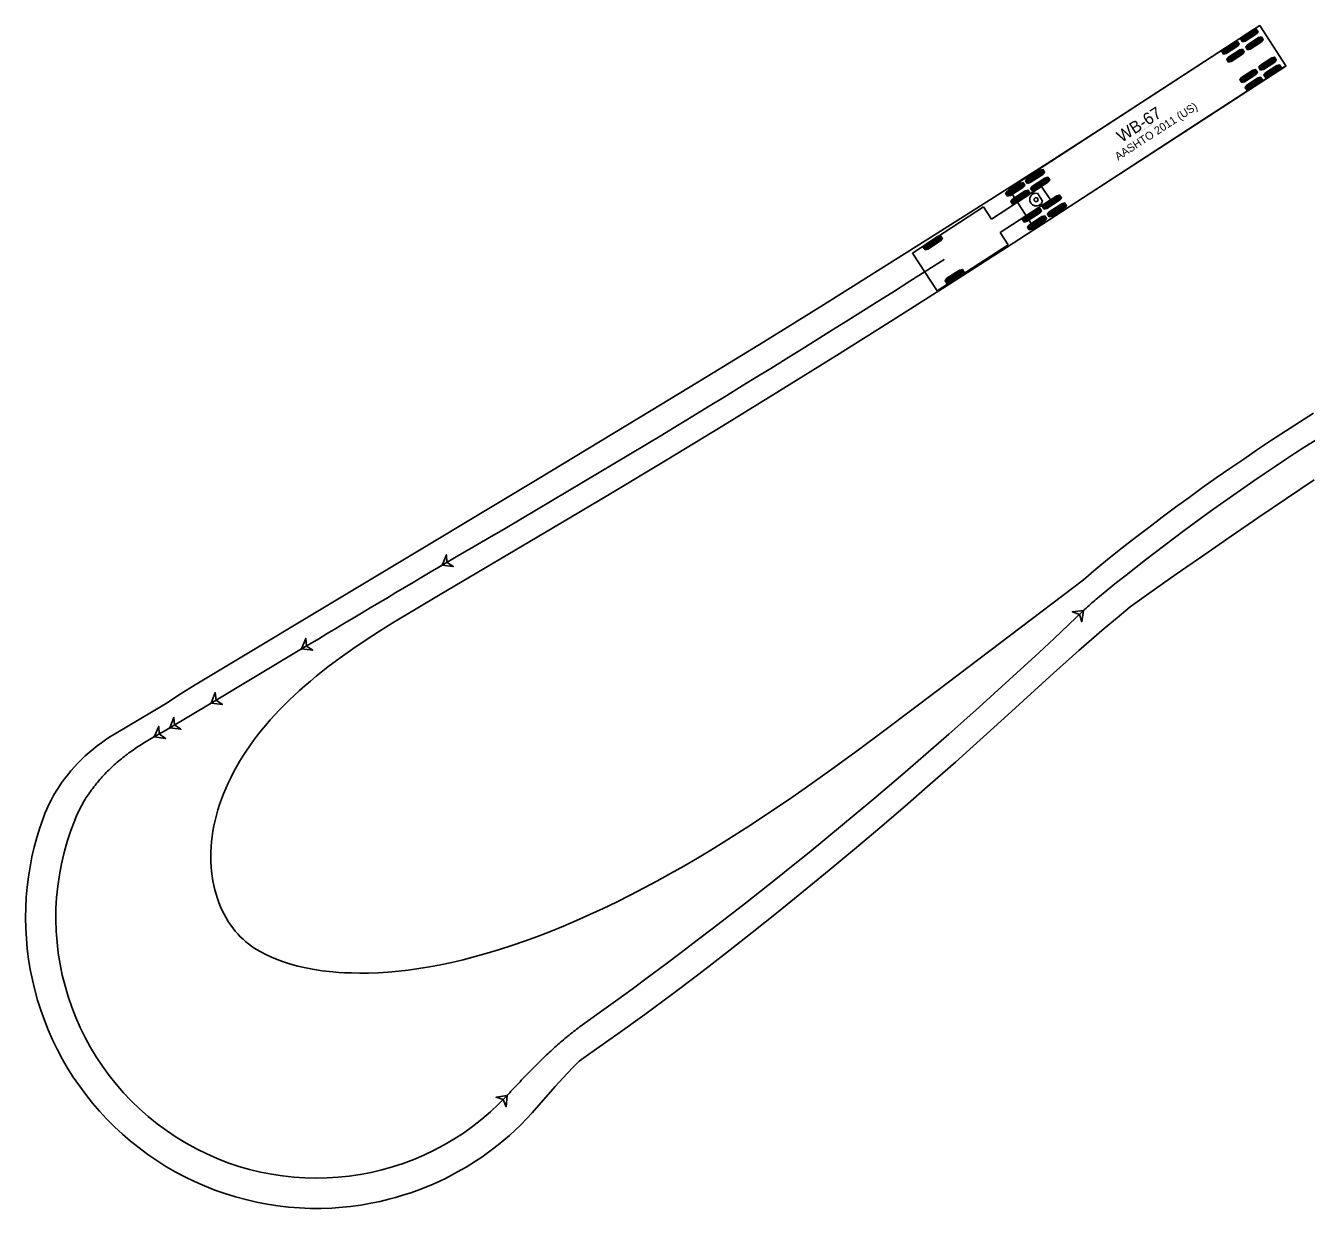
# Model space of a CAD drawing. Extents: x 2175591 to 2194071, y 76570 to 86955.
# Drawn here: x 2175590.5 to 2175817.3, y 76570.3 to 76779.7 of the extents above; entities that cross this region are included whole.
import ezdxf

# ---------------------------------------------------------------- set-up
doc = ezdxf.new("R2010")
doc.units = 0
doc.layers.add('C-UTIL-STRM-TEXT', color=7, linetype='Continuous')

msp = doc.modelspace()

# ---------------------------------------------------------------- linework, layer by layer
at = {"layer": 'C-UTIL-STRM-TEXT'}
for p, q in [((2175809.01, 76779.7), (2175764.58, 76750.82)), ((2175805.66, 76777.25), (2175808.43, 76779.05)), ((2175805.78, 76777.06), (2175808.55, 76778.86)), ((2175805.91, 76776.87), (2175808.67, 76778.66)), ((2175813.65, 76772.58), (2175809.01, 76779.7)), ((2175802.3, 76775.07), (2175805.07, 76776.87)), ((2175802.43, 76774.88), (2175805.2, 76776.68)), ((2175802.55, 76774.69), (2175805.32, 76776.48)), ((2175806.56, 76775.87), (2175809.32, 76777.66)), ((2175806.68, 76775.67), (2175809.45, 76777.47)), ((2175806.81, 76775.48), (2175809.57, 76777.28)), ((2175803.2, 76773.69), (2175805.97, 76775.48)), ((2175803.33, 76773.49), (2175806.1, 76775.29)), ((2175803.45, 76773.3), (2175806.22, 76775.1)), ((2175808.89, 76772.27), (2175811.66, 76774.07)), ((2175769.21, 76743.69), (2175813.65, 76772.58)), ((2175805.54, 76770.09), (2175808.3, 76771.89)), ((2175805.66, 76769.9), (2175808.43, 76771.7)), ((2175809.02, 76772.08), (2175811.78, 76773.88)), ((2175809.14, 76771.89), (2175811.91, 76773.69)), ((2175809.79, 76770.89), (2175812.56, 76772.69)), ((2175809.92, 76770.7), (2175812.68, 76772.5)), ((2175810.04, 76770.51), (2175812.81, 76772.31)), ((2175805.79, 76769.71), (2175808.55, 76771.51)), ((2175806.44, 76768.71), (2175809.2, 76770.51)), ((2175806.56, 76768.52), (2175809.33, 76770.32)), ((2175806.69, 76768.33), (2175809.45, 76770.13)), ((2175767.58, 76752.2), (2175770.65, 76754.2)), ((2175767.7, 76752.01), (2175770.77, 76754)), ((2175767.83, 76751.81), (2175770.9, 76753.81)), ((2175770.39, 76751.24), (2175761.5, 76745.46)), ((2175764.05, 76749.91), (2175767.13, 76751.91)), ((2175764.18, 76749.72), (2175767.25, 76751.71)), ((2175764.3, 76749.52), (2175767.38, 76751.52)), ((2175768.47, 76750.81), (2175771.55, 76752.81)), ((2175768.6, 76750.62), (2175771.67, 76752.62)), ((2175768.72, 76750.43), (2175771.8, 76752.43)), ((2175771.95, 76748.83), (2175770.39, 76751.24)), ((2175764.58, 76750.82), (2175769.21, 76743.69)), ((2175764.95, 76748.52), (2175768.03, 76750.52)), ((2175765.08, 76748.33), (2175768.15, 76750.33)), ((2175765.2, 76748.14), (2175768.28, 76750.14)), ((2175770.53, 76748.65), (2175769.64, 76750.01)), ((2175770.54, 76747.64), (2175773.61, 76749.64)), ((2175770.66, 76747.45), (2175773.74, 76749.45)), ((2175770.79, 76747.26), (2175773.86, 76749.26)), ((2175760.1, 76747.61), (2175747.52, 76739.44)), ((2175761.5, 76745.46), (2175760.1, 76747.61)), ((2175763.06, 76743.06), (2175771.95, 76748.83)), ((2175767.02, 76745.35), (2175770.09, 76747.35)), ((2175767.14, 76745.16), (2175770.21, 76747.16)), ((2175767.27, 76744.97), (2175770.34, 76746.97)), ((2175771.44, 76746.26), (2175774.51, 76748.26)), ((2175771.56, 76746.07), (2175774.64, 76748.06)), ((2175771.69, 76745.87), (2175774.76, 76747.87)), ((2175767.91, 76743.97), (2175770.99, 76745.97)), ((2175768.04, 76743.78), (2175771.11, 76745.78)), ((2175768.16, 76743.58), (2175771.24, 76745.58)), ((2175749.47, 76740.43), (2175752.54, 76742.42)), ((2175749.59, 76740.23), (2175752.66, 76742.23)), ((2175764.46, 76740.9), (2175763.06, 76743.06)), ((2175769.21, 76743.69), (2175769.21, 76743.69)), ((2175749.72, 76740.04), (2175752.79, 76742.04)), ((2175751.88, 76732.73), (2175764.46, 76740.9)), ((2175747.52, 76739.44), (2175751.88, 76732.73)), ((2175753.33, 76734.49), (2175756.4, 76736.48)), ((2175753.45, 76734.29), (2175756.53, 76736.29)), ((2175753.58, 76734.1), (2175756.65, 76736.1)), ((2175751.88, 76732.73), (2175751.88, 76732.73)), ((2175639.38, 76669.35), (2175623.38, 76659.76)), ((2175623.38, 76659.76), (2175616.04, 76655.36))]:
    msp.add_line(p, q, dxfattribs=at)
for points in [[(2175818.66, 76699.27), (2175808.87, 76692.65), (2175803.97, 76689.31), (2175799.09, 76685.95), (2175794.22, 76682.57), (2175789.38, 76679.15), (2175786.07, 76676.79), (2175783.77, 76674.88), (2175781.49, 76672.96), (2175779.23, 76671.02), (2175776.97, 76669.06), (2175774.73, 76667.08), (2175772.51, 76665.08), (2175763.77, 76657.07), (2175759.53, 76653.24), (2175755.12, 76649.29), (2175750.68, 76645.39), (2175746.22, 76641.52), (2175741.74, 76637.69), (2175737.26, 76633.9), (2175732.76, 76630.15), (2175728.26, 76626.46), (2175723.76, 76622.82), (2175719.14, 76619.13), (2175714.42, 76615.43), (2175709.68, 76611.78), (2175704.92, 76608.18), (2175700.14, 76604.64), (2175695.36, 76601.18), (2175690.6, 76597.82), (2175688.53, 76596.38), (2175687.45, 76595.29), (2175686.39, 76594.17), (2175684.3, 76591.87), (2175680.22, 76587.22), (2175679.21, 76586.13), (2175678.19, 76585.1), (2175677.18, 76584.13), (2175676.17, 76583.22), (2175675.17, 76582.36), (2175674.18, 76581.55), (2175673.2, 76580.79), (2175672.24, 76580.07), (2175671.28, 76579.39), (2175670.16, 76578.64), (2175668.49, 76577.6), (2175667.01, 76576.75), (2175665.92, 76576.16), (2175664.83, 76575.61), (2175663.86, 76575.14), (2175662.67, 76574.6), (2175660.8, 76573.83), (2175659.84, 76573.46), (2175658.7, 76573.06), (2175657.31, 76572.61), (2175655.98, 76572.21), (2175654.82, 76571.9), (2175653.29, 76571.53), (2175651.64, 76571.19), (2175649.89, 76570.89), (2175648.05, 76570.64), (2175646.63, 76570.49), (2175644.73, 76570.36), (2175642.82, 76570.3), (2175640.9, 76570.3), (2175638.99, 76570.38), (2175637.08, 76570.53), (2175635.17, 76570.75), (2175633.27, 76571.04), (2175631.39, 76571.4), (2175629.51, 76571.84), (2175627.66, 76572.34), (2175625.82, 76572.91), (2175624.01, 76573.55), (2175622.22, 76574.26), (2175620.45, 76575.03), (2175618.72, 76575.87), (2175617.02, 76576.77), (2175615.36, 76577.74), (2175613.73, 76578.76), (2175612.15, 76579.85), (2175610.61, 76580.99), (2175609.11, 76582.19), (2175607.66, 76583.44), (2175606.25, 76584.75), (2175604.9, 76586.1), (2175603.6, 76587.5), (2175602.36, 76588.95), (2175601.17, 76590.44), (2175600.04, 76591.97), (2175598.97, 76593.54), (2175597.96, 76595.15), (2175597.01, 76596.79), (2175596.12, 76598.46), (2175595.29, 76600.15), (2175594.53, 76601.88), (2175593.84, 76603.62), (2175593.21, 76605.39), (2175592.65, 76607.17), (2175592.15, 76608.97), (2175591.72, 76610.78), (2175591.35, 76612.6), (2175591.06, 76614.43), (2175590.82, 76616.26), (2175590.66, 76618.09), (2175590.56, 76619.92), (2175590.52, 76621.75), (2175590.56, 76623.57), (2175590.65, 76625.39), (2175590.81, 76627.19), (2175591.03, 76628.99), (2175591.31, 76630.76), (2175591.65, 76632.52), (2175592.06, 76634.26), (2175592.52, 76635.98), (2175593.03, 76637.68), (2175593.61, 76639.35), (2175593.92, 76640.18), (2175594.27, 76641), (2175594.64, 76641.8), (2175595.04, 76642.59), (2175595.46, 76643.38), (2175595.91, 76644.14), (2175596.39, 76644.9), (2175596.89, 76645.64), (2175597.42, 76646.37), (2175597.97, 76647.08), (2175598.55, 76647.78), (2175599.15, 76648.46), (2175599.77, 76649.12), (2175600.41, 76649.77), (2175601.08, 76650.4), (2175601.76, 76651.01), (2175602.46, 76651.6), (2175603.19, 76652.17), (2175603.93, 76652.73), (2175604.68, 76653.26), (2175605.46, 76653.78), (2175606.25, 76654.28), (2175615.26, 76659.63), (2175617.9, 76661.36), (2175620.53, 76663), (2175681.06, 76699.36), (2175701.28, 76711.57), (2175711.16, 76717.58), (2175721.21, 76723.74), (2175731.29, 76729.98), (2175741.34, 76736.26), (2175751.37, 76742.58), (2175761.37, 76748.93), (2175771.35, 76755.32), (2175781.32, 76761.74), (2175809.01, 76779.7), (2175813.65, 76772.58), (2175813.61, 76772.55), (2175813.61, 76772.55)], [(2175813.61, 76772.55), (2175764.16, 76740.42), (2175754.16, 76733.99), (2175744.14, 76727.62), (2175734.09, 76721.3), (2175724, 76715.03), (2175713.93, 76708.84), (2175704.02, 76702.82), (2175693.85, 76696.71), (2175683.71, 76690.68), (2175663.89, 76678.96), (2175655.42, 76673.93), (2175653.17, 76672.51), (2175650.79, 76670.96), (2175648.47, 76669.38), (2175646.22, 76667.78), (2175644.05, 76666.15), (2175641.96, 76664.5), (2175640.95, 76663.66), (2175639.97, 76662.82), (2175639.01, 76661.97), (2175638.09, 76661.12), (2175637.19, 76660.27), (2175636.31, 76659.41), (2175635.46, 76658.54), (2175634.63, 76657.66), (2175633.83, 76656.77), (2175633.05, 76655.87), (2175632.3, 76654.96), (2175631.58, 76654.05), (2175630.88, 76653.13), (2175630.21, 76652.21), (2175629.58, 76651.27), (2175628.97, 76650.34), (2175628.39, 76649.4), (2175627.84, 76648.45), (2175627.32, 76647.51), (2175626.83, 76646.55), (2175626.38, 76645.6), (2175625.95, 76644.65), (2175625.56, 76643.69), (2175625.2, 76642.74), (2175624.87, 76641.79), (2175624.57, 76640.84), (2175624.3, 76639.89), (2175624.07, 76638.95), (2175623.86, 76638.01), (2175623.69, 76637.08), (2175623.55, 76636.15), (2175623.44, 76635.23), (2175623.36, 76634.32), (2175623.32, 76633.42), (2175623.3, 76632.53), (2175623.32, 76631.65), (2175623.36, 76630.79), (2175623.44, 76629.93), (2175623.54, 76629.1), (2175623.67, 76628.27), (2175623.83, 76627.47), (2175624.01, 76626.68), (2175624.23, 76625.91), (2175624.47, 76625.16), (2175624.73, 76624.43), (2175625.02, 76623.71), (2175625.33, 76623.03), (2175625.66, 76622.36), (2175626.01, 76621.72), (2175626.39, 76621.1), (2175626.78, 76620.51), (2175627.2, 76619.94), (2175627.63, 76619.4), (2175628.07, 76618.88), (2175628.53, 76618.4), (2175629.01, 76617.94), (2175629.5, 76617.51), (2175629.99, 76617.11), (2175630.5, 76616.73), (2175631.01, 76616.38), (2175632.03, 76615.76), (2175633.05, 76615.22), (2175634.05, 76614.76), (2175635.03, 76614.36), (2175635.98, 76614.01), (2175636.91, 76613.71), (2175637.81, 76613.44), (2175638.7, 76613.2), (2175639.57, 76613), (2175641.29, 76612.65), (2175643.02, 76612.38), (2175644.93, 76612.17), (2175645.95, 76612.08), (2175646.99, 76612.02), (2175648.23, 76611.97), (2175649.71, 76611.94), (2175651.25, 76611.96), (2175652.96, 76612.02), (2175654.73, 76612.14), (2175656.57, 76612.3), (2175658.27, 76612.5), (2175660.15, 76612.76), (2175662.02, 76613.07), (2175663.96, 76613.43), (2175665.96, 76613.85), (2175668, 76614.33), (2175670.1, 76614.87), (2175672.23, 76615.46), (2175674.4, 76616.12), (2175676.61, 76616.83), (2175678.86, 76617.61), (2175681.13, 76618.44), (2175683.42, 76619.32), (2175685.74, 76620.26), (2175688.07, 76621.26), (2175690.42, 76622.3), (2175692.78, 76623.4), (2175695.15, 76624.54), (2175697.53, 76625.73), (2175699.91, 76626.97), (2175702.29, 76628.24), (2175704.68, 76629.56), (2175707.06, 76630.91), (2175709.45, 76632.31), (2175711.83, 76633.73), (2175714.2, 76635.19), (2175716.61, 76636.71), (2175719.01, 76638.25), (2175721.4, 76639.83), (2175723.79, 76641.43), (2175726.17, 76643.06), (2175728.53, 76644.71), (2175733.25, 76648.07), (2175737.95, 76651.5), (2175742.62, 76654.97), (2175751.95, 76662), (2175777.8, 76681.56), (2175780.03, 76683.55), (2175782.34, 76685.41), (2175784.67, 76687.25), (2175787.01, 76689.07), (2175789.36, 76690.87), (2175791.73, 76692.66), (2175794.1, 76694.42), (2175796.49, 76696.17), (2175798.89, 76697.9), (2175801.31, 76699.61), (2175803.73, 76701.3), (2175806.17, 76702.97), (2175808.61, 76704.63), (2175811.09, 76706.28), (2175813.57, 76707.9), (2175816.05, 76709.5), (2175818.55, 76711.09)], [(2175753.06, 76738.26), (2175752.78, 76738.08), (2175752.5, 76737.9)], [(2175664.26, 76684.18), (2175663.97, 76684.01), (2175663.68, 76683.84)], [(2175777.81, 76676.13), (2175778.05, 76676.36), (2175778.3, 76676.59), (2175778.54, 76676.82), (2175778.79, 76677.04), (2175779.04, 76677.27), (2175779.29, 76677.49), (2175779.54, 76677.71), (2175779.79, 76677.92), (2175780.04, 76678.14), (2175780.3, 76678.35)], [(2175613.31, 76653.8), (2175613.02, 76653.64), (2175612.73, 76653.47), (2175612.44, 76653.3), (2175612.15, 76653.13), (2175611.86, 76652.96), (2175611.58, 76652.79), (2175611.3, 76652.61), (2175611.02, 76652.44), (2175610.73, 76652.26), (2175610.46, 76652.07), (2175610.18, 76651.89), (2175609.9, 76651.7), (2175609.63, 76651.51), (2175609.36, 76651.32), (2175609.09, 76651.12), (2175608.82, 76650.93), (2175608.55, 76650.73), (2175608.28, 76650.53), (2175608.02, 76650.32), (2175607.76, 76650.12), (2175607.5, 76649.91), (2175607.24, 76649.7), (2175606.99, 76649.48), (2175606.73, 76649.27), (2175606.48, 76649.05), (2175606.23, 76648.82), (2175605.99, 76648.6), (2175605.74, 76648.37), (2175605.5, 76648.14), (2175605.26, 76647.91), (2175605.02, 76647.68), (2175604.79, 76647.44), (2175604.56, 76647.2), (2175604.33, 76646.96), (2175604.1, 76646.71), (2175603.88, 76646.47), (2175603.66, 76646.21), (2175603.44, 76645.96), (2175603.23, 76645.71), (2175603.02, 76645.45), (2175602.81, 76645.19), (2175602.6, 76644.93), (2175602.4, 76644.66), (2175602.2, 76644.39), (2175602.01, 76644.12), (2175601.82, 76643.85), (2175601.63, 76643.57), (2175601.44, 76643.3), (2175601.26, 76643.02), (2175601.09, 76642.73), (2175600.91, 76642.45), (2175600.74, 76642.16), (2175600.58, 76641.87), (2175600.42, 76641.58), (2175600.26, 76641.29), (2175600.1, 76640.99), (2175599.96, 76640.69), (2175599.81, 76640.39), (2175599.67, 76640.09), (2175599.53, 76639.79), (2175599.4, 76639.48), (2175599.27, 76639.17)], [(2175616.04, 76655.36), (2175615.76, 76655.19), (2175615.47, 76655.02), (2175615.18, 76654.85), (2175614.89, 76654.69)], [(2175675.77, 76590.3), (2175676, 76590.54), (2175676.22, 76590.78), (2175676.45, 76591.03), (2175676.68, 76591.27), (2175676.91, 76591.51), (2175677.14, 76591.76), (2175677.36, 76592), (2175677.59, 76592.24), (2175677.82, 76592.48), (2175678.05, 76592.72), (2175678.28, 76592.97), (2175678.51, 76593.21), (2175678.74, 76593.45), (2175678.97, 76593.69), (2175679.2, 76593.93), (2175679.44, 76594.17), (2175679.67, 76594.41), (2175679.9, 76594.65), (2175680.13, 76594.88), (2175680.37, 76595.12), (2175680.6, 76595.36), (2175680.84, 76595.59), (2175681.07, 76595.83), (2175681.31, 76596.06), (2175681.55, 76596.3), (2175681.79, 76596.53), (2175682.03, 76596.76), (2175682.27, 76597), (2175682.51, 76597.23), (2175682.75, 76597.46), (2175682.99, 76597.68), (2175683.23, 76597.91), (2175683.48, 76598.14), (2175683.72, 76598.37), (2175683.97, 76598.59), (2175684.22, 76598.81), (2175684.46, 76599.04), (2175684.71, 76599.26), (2175684.96, 76599.48), (2175685.21, 76599.7), (2175685.47, 76599.91), (2175685.72, 76600.13), (2175685.98, 76600.35), (2175686.23, 76600.56), (2175686.49, 76600.77), (2175686.75, 76600.98), (2175687.01, 76601.19), (2175687.27, 76601.4), (2175687.53, 76601.6), (2175687.79, 76601.81), (2175688.06, 76602.01), (2175688.32, 76602.21), (2175688.59, 76602.41), (2175688.86, 76602.61), (2175689.13, 76602.8)]]:
    msp.add_lwpolyline(points, dxfattribs=at)
for points in [[(2175805.94, 76776.82), (2175805.63, 76777.3), (2175805.92, 76777.69), (2175807.91, 76778.99), (2175808.39, 76779.1), (2175808.71, 76778.62), (2175808.41, 76778.22), (2175806.42, 76776.93)], [(2175802.59, 76774.64), (2175802.27, 76775.12), (2175802.57, 76775.51), (2175804.56, 76776.81), (2175805.04, 76776.92), (2175805.35, 76776.44), (2175805.06, 76776.04), (2175803.07, 76774.75)], [(2175806.84, 76775.43), (2175806.53, 76775.91), (2175806.82, 76776.31), (2175808.81, 76777.61), (2175809.29, 76777.71), (2175809.61, 76777.23), (2175809.31, 76776.84), (2175807.32, 76775.54)], [(2175803.48, 76773.25), (2175803.17, 76773.73), (2175803.47, 76774.13), (2175805.46, 76775.43), (2175805.94, 76775.53), (2175806.25, 76775.05), (2175805.96, 76774.66), (2175803.97, 76773.36)], [(2175809.17, 76771.84), (2175808.86, 76772.32), (2175809.15, 76772.72), (2175811.15, 76774.01), (2175811.63, 76774.12), (2175811.94, 76773.64), (2175811.65, 76773.25), (2175809.65, 76771.95)], [(2175805.82, 76769.66), (2175805.51, 76770.14), (2175805.8, 76770.54), (2175807.79, 76771.83), (2175808.27, 76771.94), (2175808.59, 76771.46), (2175808.29, 76771.07), (2175806.3, 76769.77)], [(2175810.07, 76770.46), (2175809.76, 76770.94), (2175810.05, 76771.34), (2175812.05, 76772.63), (2175812.53, 76772.74), (2175812.84, 76772.26), (2175812.55, 76771.86), (2175810.55, 76770.57)], [(2175806.72, 76768.28), (2175806.41, 76768.76), (2175806.7, 76769.16), (2175808.69, 76770.45), (2175809.17, 76770.56), (2175809.48, 76770.08), (2175809.19, 76769.68), (2175807.2, 76768.39)], [(2175767.86, 76751.77), (2175767.54, 76752.24), (2175767.88, 76752.67), (2175770.09, 76754.11), (2175770.62, 76754.24), (2175770.93, 76753.76), (2175770.59, 76753.34), (2175768.38, 76751.9)], [(2175764.34, 76749.48), (2175764.02, 76749.96), (2175764.36, 76750.38), (2175766.57, 76751.82), (2175767.1, 76751.95), (2175767.41, 76751.47), (2175767.07, 76751.05), (2175764.86, 76749.61)], [(2175768.76, 76750.38), (2175768.44, 76750.86), (2175768.78, 76751.29), (2175770.99, 76752.72), (2175771.52, 76752.86), (2175771.83, 76752.38), (2175771.49, 76751.96), (2175769.28, 76750.52)], [(2175765.23, 76748.09), (2175764.92, 76748.57), (2175765.26, 76749), (2175767.47, 76750.44), (2175768, 76750.57), (2175768.31, 76750.09), (2175767.97, 76749.67), (2175765.76, 76748.23)], [(2175770.82, 76747.21), (2175770.51, 76747.69), (2175770.84, 76748.11), (2175773.06, 76749.55), (2175773.58, 76749.69), (2175773.89, 76749.21), (2175773.56, 76748.78), (2175771.34, 76747.34)], [(2175767.3, 76744.92), (2175766.98, 76745.4), (2175767.32, 76745.82), (2175769.53, 76747.26), (2175770.06, 76747.4), (2175770.37, 76746.92), (2175770.03, 76746.49), (2175767.82, 76745.06)], [(2175771.72, 76745.83), (2175771.41, 76746.31), (2175771.74, 76746.73), (2175773.96, 76748.17), (2175774.48, 76748.3), (2175774.79, 76747.82), (2175774.45, 76747.4), (2175772.24, 76745.96)], [(2175768.2, 76743.54), (2175767.88, 76744.02), (2175768.22, 76744.44), (2175770.43, 76745.88), (2175770.96, 76746.02), (2175771.27, 76745.54), (2175770.93, 76745.11), (2175768.72, 76743.67)], [(2175749.75, 76739.99), (2175749.43, 76740.47), (2175749.77, 76740.9), (2175751.98, 76742.34), (2175752.51, 76742.47), (2175752.82, 76741.99), (2175752.48, 76741.57), (2175750.27, 76740.13)], [(2175753.61, 76734.05), (2175753.29, 76734.53), (2175753.63, 76734.96), (2175755.84, 76736.4), (2175756.37, 76736.53), (2175756.68, 76736.05), (2175756.34, 76735.63), (2175754.13, 76734.19)], [(2175664.26, 76684.18), (2175666.24, 76683.92), (2175665.12, 76684.68), (2175665.02, 76686.03)], [(2175777.81, 76676.13), (2175775.83, 76675.92), (2175777.09, 76675.44), (2175777.51, 76674.16)], [(2175639.38, 76669.35), (2175641.37, 76669.12), (2175640.24, 76669.86), (2175640.12, 76671.21)], [(2175623.38, 76659.76), (2175625.37, 76659.53), (2175624.24, 76660.27), (2175624.11, 76661.62)], [(2175616.04, 76655.36), (2175618.03, 76655.13), (2175616.9, 76655.88), (2175616.78, 76657.22)], [(2175613.31, 76653.8), (2175615.29, 76653.51), (2175614.18, 76654.29), (2175614.1, 76655.64)], [(2175675.77, 76590.3), (2175673.8, 76589.97), (2175675.09, 76589.56), (2175675.58, 76588.3)]]:
    msp.add_lwpolyline(points, close=True, dxfattribs=at)
for centre, radius in [((2175769.41, 76748.89), 0.34), ((2175752.5, 76737.9), 0.0417), ((2175752.5, 76737.9), 0.0417), ((2175753.06, 76738.26), 0.0417), ((2175663.68, 76683.84), 0.0417), ((2175663.68, 76683.84), 0.0417), ((2175664.26, 76684.18), 0.0417), ((2175664.26, 76684.18), 0.0417), ((2175780.3, 76678.35), 0.0417), ((2175780.3, 76678.35), 0.0417), ((2175777.81, 76676.13), 0.0417), ((2175777.81, 76676.13), 0.0417), ((2175639.38, 76669.35), 0.0417), ((2175639.38, 76669.35), 0.0417), ((2175623.38, 76659.76), 0.0417), ((2175623.38, 76659.76), 0.0417), ((2175613.31, 76653.8), 0.0417), ((2175613.31, 76653.8), 0.0417), ((2175614.89, 76654.69), 0.0417), ((2175614.89, 76654.69), 0.0417), ((2175616.04, 76655.36), 0.0417), ((2175616.04, 76655.36), 0.0417), ((2175599.27, 76639.17), 0.0417), ((2175599.27, 76639.17), 0.0417), ((2175689.13, 76602.8), 0.0417), ((2175689.13, 76602.8), 0.0417), ((2175675.77, 76590.3), 0.0417), ((2175675.77, 76590.3), 0.0417)]:
    msp.add_circle(centre, radius, dxfattribs=at)
for centre, radius, start, end in [((2175769.41, 76748.89), 1.14, 78.0247, 348.0247), ((2174449.39, 78778.97), 2421.58, 300.1115, 302.55593), ((2176032.69, 76370.73), 397.91, 119.3977, 129.3671), ((2179566.25, 70115.26), 7640.44, 120.71568, 120.927872), ((2175219.61, 77260.92), 808.44, 305.5055, 313.66792), ((2175234.33, 77329.92), 775.09, 299.2712, 299.40553), ((2175642.04, 76621.8), 46.16, 157.8954, 316.9499)]:
    msp.add_arc(centre, radius, start, end, dxfattribs=at)

# ---------------------------------------------------------------- texts
for s, height, p in [('WB-67', 2.125, (2175784.56, 76758.94)), ('AASHTO 2011 (US)', 1.4167, (2175783.93, 76755.79)), ('(c) 2019 Transoft Solutions, Inc. All rights reserved.', 0.085, (2175787.68, 76760.72))]:
    msp.add_text(s, height=height, rotation=33.0247, dxfattribs=at).set_placement(p)

doc.saveas('drawing.dxf')
